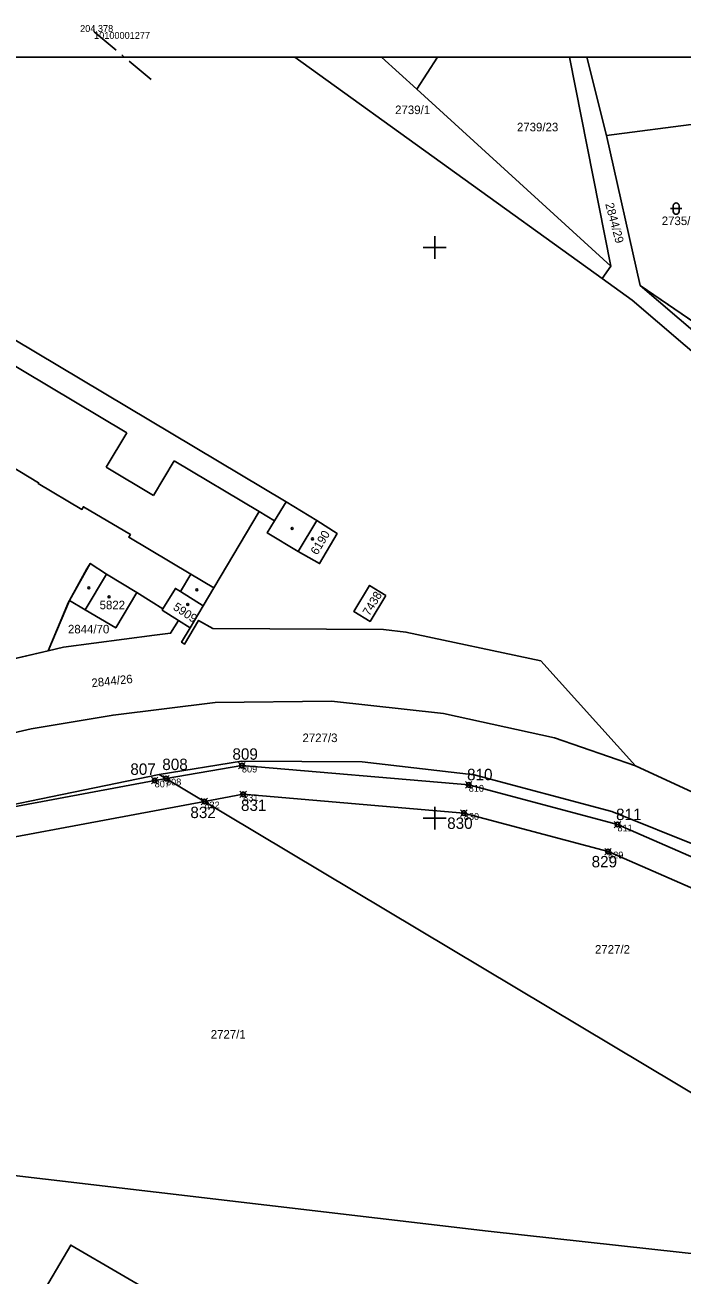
# Model space of a CAD drawing. Extents: x -800194 to -799078, y -1007177 to -1006597.
# Drawn here: x -800071.9 to -799956.6, y -1006980.2 to -1006761 of the extents above; entities that cross this region are included whole.
import ezdxf

# ---------------------------------------------------------------- set-up
doc = ezdxf.new("R2010")
doc.units = 0
for name, color, linetype in [('Dočasné zábory', 7, 'Continuous'), ('Legenda 1', 7, 'Continuous'), ('Ramove udaje', 7, 'Continuous'), ('Vrstva 53', 7, 'Continuous'), ('Vrstva 55', 7, 'Continuous'), ('Vrstva 56', 7, 'Continuous'), ('Vrstva 57', 7, 'Continuous'), ('Vrstva 58', 7, 'Continuous'), ('Vrstva 59', 7, 'Continuous'), ('Vrstva 60', 7, 'Continuous'), ('Vrstva 61', 7, 'Continuous'), ('Vrstva 63', 7, 'Continuous')]:
    doc.layers.add(name, color=color, linetype=linetype)

msp = doc.modelspace()

# ---------------------------------------------------------------- linework, layer by layer
at = {"layer": 'Dočasné zábory'}
for p, q in [((-800034.39, -1006891.36), (-800033.25, -1006890.23)), ((-800034.39, -1006890.23), (-800033.25, -1006891.36)), ((-800049.69, -1006893.98), (-800048.56, -1006892.85)), ((-800049.69, -1006892.85), (-800048.56, -1006893.98)), ((-800047.7, -1006893.64), (-800046.57, -1006892.51)), ((-800047.7, -1006892.51), (-800046.57, -1006893.64)), ((-799994.59, -1006894.74), (-799993.46, -1006893.61)), ((-799994.59, -1006893.61), (-799993.46, -1006894.74)), ((-800034.17, -1006896.4), (-800033.04, -1006895.27)), ((-800034.17, -1006895.27), (-800033.04, -1006896.4)), ((-800040.96, -1006897.67), (-800039.83, -1006896.53)), ((-800040.96, -1006896.53), (-800039.83, -1006897.67)), ((-799995.46, -1006899.69), (-799994.33, -1006898.56)), ((-799995.46, -1006898.56), (-799994.33, -1006899.69)), ((-799968.5, -1006901.7), (-799967.37, -1006900.57)), ((-799968.5, -1006900.57), (-799967.37, -1006901.7)), ((-799970.15, -1006906.43), (-799969.02, -1006905.3)), ((-799970.15, -1006905.3), (-799969.02, -1006906.43))]:
    msp.add_line(p, q, dxfattribs=at)
msp.add_lwpolyline([(-799934.68, -1006921.09), (-799969.58, -1006905.87), (-799994.89, -1006899.12), (-800033.61, -1006895.83), (-800040.4, -1006897.1), (-800095.58, -1006907.39), (-800115.82, -1006916.46), (-800120.68, -1006918.64), (-800132.21, -1006926.78), (-800151.89, -1006932.45), (-800163.09, -1006935.68), (-800154.78, -1006924.73), (-800141.19, -1006923.2), (-800136.27, -1006922.64), (-800124.59, -1006914.47), (-800109.03, -1006907.82), (-800095.49, -1006902.03), (-800049.12, -1006893.41), (-800047.13, -1006893.07), (-800033.82, -1006890.8), (-799994.03, -1006894.18), (-799967.93, -1006901.13), (-799932.44, -1006916.61)], dxfattribs=at)
for centre in [(-800033.82, -1006890.8), (-800049.12, -1006893.41), (-800047.13, -1006893.07), (-799994.03, -1006894.18), (-800033.61, -1006895.83), (-800040.4, -1006897.1), (-799994.89, -1006899.12), (-799967.93, -1006901.13), (-799969.58, -1006905.87)]:
    msp.add_circle(centre, 0.4, dxfattribs=at)
at = {"layer": 'Legenda 1'}
msp.add_lwpolyline([(-800193.4, -1007176.65), (-799312.4, -1007176.65), (-799312.4, -1006766.65), (-800193.4, -1006766.65)], close=True, dxfattribs=at)
at = {"layer": 'Ramove udaje'}
for p, q in [((-800000, -1006798), (-800000, -1006802)), ((-800002, -1006800), (-800000, -1006800)), ((-800000, -1006800), (-799998, -1006800)), ((-800000, -1006898), (-800000, -1006902)), ((-800002, -1006900), (-800000, -1006900)), ((-800000, -1006900), (-799998, -1006900))]:
    msp.add_line(p, q, dxfattribs=at)
at = {"layer": 'Vrstva 53'}
for points in [[(-799973.31, -1006766.65), (-799969.88, -1006780.37), (-799963.94, -1006806.68), (-799940.15, -1006822.89)], [(-799954.76, -1006895.45), (-799964.79, -1006890.84), (-799981.37, -1006872.46), (-800005.05, -1006867.41), (-800009, -1006866.96), (-800038.94, -1006866.77), (-800041.43, -1006865.34), (-800043.88, -1006869.49), (-800044.4, -1006869.18), (-800042.89, -1006866.63), (-800044.93, -1006865.34), (-800047.78, -1006863.53), (-800047.67, -1006863.34), (-800049.72, -1006862.02), (-800052.27, -1006860.45), (-800057.6, -1006857.24), (-800060.43, -1006855.37), (-800064.08, -1006861.85), (-800067.83, -1006870.66), (-800083.75, -1006874.38)]]:
    msp.add_lwpolyline(points, dxfattribs=at)
at = {"layer": 'Vrstva 55'}
for p, q in [((-800024.53, -1006766.65), (-799970.63, -1006805.46)), ((-800003.16, -1006772.25), (-800009.31, -1006766.65)), ((-800003.16, -1006772.25), (-799999.51, -1006766.65)), ((-799969.12, -1006803.26), (-799976.33, -1006766.65)), ((-799973.31, -1006766.65), (-799969.88, -1006780.37)), ((-799969.12, -1006803.26), (-800003.16, -1006772.25)), ((-799953.68, -1006778.26), (-799969.88, -1006780.37)), ((-799969.88, -1006780.37), (-799963.94, -1006806.68)), ((-799970.63, -1006805.46), (-799969.12, -1006803.26)), ((-799970.63, -1006805.46), (-799965.36, -1006809.25)), ((-799963.94, -1006806.68), (-799940.15, -1006822.89)), ((-799965.36, -1006809.25), (-799930.99, -1006838.59)), ((-800023.97, -1006853.3), (-800020.66, -1006847.86)), ((-800042.78, -1006857.25), (-800038.76, -1006859.64)), ((-800042.89, -1006866.63), (-800044.93, -1006865.34)), ((-800067.83, -1006870.66), (-800083.75, -1006874.38)), ((-799905.8, -1006977.56), (-800048.34, -1006892.35))]:
    msp.add_line(p, q, dxfattribs=at)
for points in [[(-800020.66, -1006847.86), (-800026.06, -1006844.58), (-800089.97, -1006806.47), (-800092.01, -1006809.83), (-800100.11, -1006823.15)], [(-799922.45, -1006841.18), (-799927.36, -1006837.92), (-799963.94, -1006806.68)], [(-800077.33, -1006838.69), (-800076.4, -1006837.12), (-800069.48, -1006841.22), (-800069.56, -1006841.35), (-800061.89, -1006845.9), (-800061.61, -1006845.43), (-800053.39, -1006850.31), (-800053.68, -1006850.78), (-800042.78, -1006857.25)], [(-800038.76, -1006859.64), (-800030.81, -1006846.28), (-800028.08, -1006847.9), (-800029.37, -1006850.02), (-800023.97, -1006853.3)], [(-800020.66, -1006847.86), (-800017.12, -1006850.15), (-800020.18, -1006855.39), (-800023.97, -1006853.3)], [(-800064.08, -1006861.85), (-800061.02, -1006856.31), (-800060.43, -1006855.37), (-800057.6, -1006857.24), (-800052.27, -1006860.45)], [(-800047.67, -1006863.34), (-800045.49, -1006859.74), (-800044.59, -1006860.3), (-800042.78, -1006857.25)], [(-800052.27, -1006860.45), (-800055.96, -1006866.67), (-800061.32, -1006863.49), (-800064.08, -1006861.85)], [(-800052.27, -1006860.45), (-800049.72, -1006862.02), (-800047.67, -1006863.34)], [(-800042.89, -1006866.63), (-800040.61, -1006862.78), (-800038.76, -1006859.64)], [(-800008.55, -1006860.96), (-800011.33, -1006865.52), (-800014.19, -1006863.79), (-800011.42, -1006859.22), (-800008.55, -1006860.96)], [(-800067.83, -1006870.66), (-800064.25, -1006862.16), (-800064.08, -1006861.85)], [(-800047.67, -1006863.34), (-800047.78, -1006863.53), (-800044.93, -1006865.34)], [(-800044.93, -1006865.34), (-800046.33, -1006867.59), (-800049.13, -1006867.95), (-800065.09, -1006870.02), (-800067.83, -1006870.66)], [(-799964.79, -1006890.84), (-799981.37, -1006872.46), (-800005.05, -1006867.41), (-800009, -1006866.96), (-800038.94, -1006866.77), (-800041.43, -1006865.34), (-800043.88, -1006869.49), (-800044.4, -1006869.18), (-800042.89, -1006866.63)], [(-799964.79, -1006890.84), (-799979.01, -1006885.96), (-799998.45, -1006881.67), (-800018.08, -1006879.48), (-800038.51, -1006879.76), (-800056.43, -1006881.95), (-800070.76, -1006884.38), (-800080.47, -1006886.59), (-800089.79, -1006889.63), (-800088.91, -1006893.34), (-800105.12, -1006899.41), (-800124.67, -1006911.59), (-800137.62, -1006920.11), (-800154.3, -1006934.53), (-800165.04, -1006947.7)], [(-799901.69, -1006974.63), (-799900.54, -1006973.82), (-799898.31, -1006947.43), (-799904.63, -1006933.89), (-799915, -1006924.46), (-799932.22, -1006915.03), (-799953.17, -1006905.18), (-799968.93, -1006898.86), (-799993.08, -1006892.39), (-800012.71, -1006890.11), (-800033.89, -1006890), (-800048.34, -1006892.35)], [(-799839.73, -1006961.33), (-799877.87, -1006942.17), (-799936.47, -1006903.99), (-799954.76, -1006895.45), (-799964.79, -1006890.84)], [(-800048.34, -1006892.35), (-800095.49, -1006902.03), (-800108.2, -1006906.76), (-800120.56, -1006922.5)], [(-800126.38, -1006954.46), (-800114.82, -1006956.57), (-800087.75, -1006960.99), (-799990.59, -1006972.38), (-799910.85, -1006981.15)], [(-800069.59, -1006984.65), (-800063.85, -1006974.82), (-800037.33, -1006990.25), (-800033.78, -1006992.42), (-800023.89, -1006998.18), (-800020.27, -1007000.33), (-799995.43, -1007014.87), (-800001.26, -1007024.83), (-800026.05, -1007010.11), (-800029.71, -1007008.06), (-800039.6, -1007002.32), (-800043.23, -1007000.2), (-800069.59, -1006984.65)]]:
    msp.add_lwpolyline(points, dxfattribs=at)
at = {"layer": 'Vrstva 56'}
for p, q in [((-800092.01, -1006809.83), (-800054.01, -1006832.46)), ((-800054.01, -1006832.46), (-800057.61, -1006838.51)), ((-800057.61, -1006838.51), (-800049.33, -1006843.44)), ((-800049.33, -1006843.44), (-800045.73, -1006837.39)), ((-800045.73, -1006837.39), (-800030.81, -1006846.28)), ((-800026.06, -1006844.58), (-800028.08, -1006847.9)), ((-800061.32, -1006863.49), (-800057.6, -1006857.24)), ((-800044.59, -1006860.3), (-800040.61, -1006862.78))]:
    msp.add_line(p, q, dxfattribs=at)
at = {"layer": 'Vrstva 58'}
for p, q in [((-799958.14, -1006792.67), (-799958.14, -1006793.67)), ((-799957.14, -1006793.67), (-799957.14, -1006792.67)), ((-799958.64, -1006793.17), (-799956.64, -1006793.17))]:
    msp.add_line(p, q, dxfattribs=at)
for centre, start, end in [((-799957.64, -1006792.67), 0, 180), ((-799957.64, -1006793.67), 180, 359.9879)]:
    msp.add_arc(centre, 0.5, start, end, dxfattribs=at)
at = {"layer": 'Vrstva 59'}
for centre in [(-800025.01, -1006849.23), (-800021.44, -1006851.08), (-800060.68, -1006859.65), (-800041.71, -1006860), (-800057.13, -1006861.24), (-800043.33, -1006862.55)]:
    msp.add_circle(centre, 0.175, dxfattribs=at)
at = {"layer": 'Vrstva 60'}
for p, q in [((-800059.75, -1006762.22), (-800059.75, -1006762.22)), ((-800033.82, -1006890.8), (-800033.82, -1006890.8)), ((-800049.12, -1006893.41), (-800049.12, -1006893.41)), ((-800047.13, -1006893.07), (-800047.13, -1006893.07)), ((-800033.61, -1006895.83), (-800033.61, -1006895.83)), ((-799994.03, -1006894.18), (-799994.03, -1006894.18)), ((-800040.4, -1006897.1), (-800040.4, -1006897.1)), ((-799994.89, -1006899.12), (-799994.89, -1006899.12)), ((-799967.93, -1006901.13), (-799967.93, -1006901.13)), ((-799969.58, -1006905.87), (-799969.58, -1006905.87))]:
    msp.add_line(p, q, dxfattribs=at)
at = {"layer": 'Vrstva 63'}
for p, q in [((-800059.75, -1006762.22), (-800055.9, -1006765.42)), ((-800054.9, -1006766.25), (-800054.6, -1006766.51)), ((-800053.6, -1006767.34), (-800049.75, -1006770.53))]:
    msp.add_line(p, q, dxfattribs=at)

# ---------------------------------------------------------------- texts
at = {"layer": 'Dočasné zábory'}
for s, p in [('809', (-800035.48, -1006889.77)), ('807', (-800053.39, -1006892.42)), ('808', (-800047.78, -1006891.58)), ('810', (-799994.32, -1006893.36)), ('832', (-800042.86, -1006900)), ('831', (-800033.98, -1006898.74)), ('830', (-799997.81, -1006901.89)), ('811', (-799968.18, -1006900.35)), ('829', (-799972.47, -1006908.63))]:
    msp.add_text(s, height=2, rotation=360, dxfattribs=at).set_placement(p)
at = {"layer": 'Vrstva 57'}
for s, p in [('2739/1', (-800006.94, -1006776.62)), ('2739/23', (-799985.57, -1006779.64)), ('2735/1', (-799960.17, -1006796.07)), ('5822', (-800058.78, -1006863.4)), ('2844/70', (-800064.33, -1006867.63)), ('2727/3', (-800023.19, -1006886.68)), ('2727/2', (-799971.88, -1006923.75)), ('2727/1', (-800039.29, -1006938.64))]:
    msp.add_text(s, height=1.5, dxfattribs=at).set_placement(p)
for s, rotation, p in [('2844/29', 285, (-799970.09, -1006792.38)), ('6190', 59, (-800020.6, -1006854)), ('7438', 59, (-800011.47, -1006864.68)), ('5909', 326, (-800046.03, -1006863.34)), ('2844/26', 6, (-800060.13, -1006877.07))]:
    msp.add_text(s, height=1.5, rotation=rotation, dxfattribs=at).set_placement(p)
at = {"layer": 'Vrstva 60'}
for s, p in [('10100001277', (-800059.75, -1006763.43)), ('809', (-800033.82, -1006892)), ('807', (-800049.12, -1006894.61)), ('808', (-800047.13, -1006894.27)), ('831', (-800033.61, -1006897.03)), ('810', (-799994.03, -1006895.38)), ('832', (-800040.4, -1006898.3)), ('830', (-799994.89, -1006900.32)), ('811', (-799967.93, -1006902.33)), ('829', (-799969.58, -1006907.07))]:
    msp.add_text(s, height=1.2, dxfattribs=at).set_placement(p)
at = {"layer": 'Vrstva 61'}
msp.add_text('204.378', height=1.2, dxfattribs=at).set_placement((-800062.2, -1006762.22))

doc.saveas('drawing.dxf')
